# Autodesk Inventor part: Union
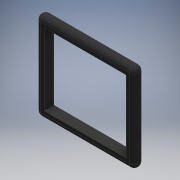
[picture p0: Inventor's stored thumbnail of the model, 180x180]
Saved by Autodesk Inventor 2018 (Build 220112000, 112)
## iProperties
Created: 2022-01
Part Number: Union
Material: Caucho, Silicona
Document SubType Name: Modeling
Designer: Asus
Density: 1.25 g/cm^3
Appearance: Goma - Negro
Author: Asus
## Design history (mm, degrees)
sketch "Boceto1"
  geometry: L1 (135, 120)-(-135, 120); L2 (-135, 120)-(-135, -120); L3 (-135, -120)-(135, -120); L4 (135, -120)-(135, 120); L5 (135, 120)-(-135, -120); L6 (-135, 120)-(135, -120); L7 (125, 110)-(-125, 110); L8 (-125, 110)-(-125, -110); L9 (-125, -110)-(125, -110); L10 (125, -110)-(125, 110); L11 (125, 110)-(-125, -110); L12 (-125, 110)-(125, -110); 1 further point
  constraints: 24 end point, 4 midpoint, 4 parallel, 2 horizontal, 2 perpendicular
  dimensions: "d0" = 270 distance of L3.end L2.end; "d1" = 240 distance of L2.end L1.end; "d2" = 250 distance of L9.end L8.end; "d3" = 220 distance of L8.end L7.end
extrude "Extrusión1" new body sketch "Boceto1" distance "d4" = 30; taper "d5" = 0 deg
sketch "Boceto2"
  geometry: L1 (0, 0)-(0, 30) reference; L2 (0, 30)-(0, 0); A1 r 15 centre (0, 15) between (0, 30) and (0, 0); 1 further point
  constraints: 2 end point, 2 point on circle, 1 centre point, 1 collinear, 1 midpoint
extrude "Extrusión2" join sketch "Boceto2" distance "d6" = 270; taper "d7" = 0 deg
revolve "Revolución1" stored, may be unused: angle "d8" = 90 deg
sketch "Boceto4"
  geometry: L1 (0, 30)-(0, 0); L2 (0, 0)-(0, 30) reference; A1 r 15 centre (0, 15) between (0, 30) and (0, 0); 1 further point
  constraints: 4 end point, 2 point on circle, 1 centre point, 1 midpoint
extrude "Extrusión3" join sketch "Boceto4" distance "d10" = 240; taper "d11" = 0 deg
revolve "Revolución2" stored, may be unused: angle "d12" = 90 deg
sketch "Boceto5"
  geometry: L1 (0, 0)-(0, 30) reference; L2 (0, 30)-(0, 0); A1 r 15 centre (0, 15) between (0, 30) and (0, 0); 1 further point
  constraints: 2 end point, 2 point on circle, 1 centre point, 1 midpoint, 1 vertical
extrude "Extrusión4" join sketch "Boceto5" distance "d13" = 270; taper "d14" = 0 deg
revolve "Revolución3" stored, may be unused: angle "d15" = 90 deg
sketch "Boceto8"
  geometry: L1 (0, 30)-(0, 0) reference; L2 (0, 30)-(0, 0); A1 r 15 centre (0, 15) between (0, 30) and (0, 0); 1 further point
  constraints: 2 end point, 2 point on circle, 1 centre point, 1 collinear
extrude "Extrusión6" join sketch "Boceto8" distance "d19" = 240; taper "d20" = 0 deg
sketch "Boceto9"
  geometry: L1 (0, 30)-(0, 0) reference; L2 (0, 30)-(0, 0); A1 r 15 centre (0, 15) between (0, 30) and (0, 0) reference; A2 r 15 centre (0, 15) between (0, 30) and (0, 0); 1 further point
  constraints: 2 end point, 2 point on circle, 1 centre point, 1 coincident, 1 vertical
revolve "Revolución5" sketch "Boceto9" stored, may be unused: angle "d21" = 90 deg
node "Sólido1"
